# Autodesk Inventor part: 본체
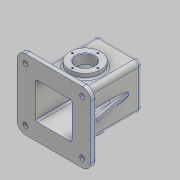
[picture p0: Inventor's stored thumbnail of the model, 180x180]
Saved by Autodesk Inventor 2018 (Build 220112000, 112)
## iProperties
Created: 2022-11
Part Number: 본체
Material: 알루미늄 6061
Document SubType Name: Modeling
Designer: home
Density: 2.7 g/cm^3
Appearance: 알루미늄 - 평지
Mass: 1126.74 g
Surface Area: 1013.84 cm^2
Volume: 417.312 cm^3
Author: home
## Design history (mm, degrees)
sketch "스케치1"
  geometry: L1 (-65, 47)-(-65, -47); L2 (-50, -62)-(50, -62); L3 (65, -47)-(65, 47); L4 (50, 62)-(-50, 62); L5 (-65, 62)-(65, -62); L6 (-65, -62)-(65, 62); A1 r 15 centre (50, 47) between (65, 47) and (50, 62); A2 r 15 centre (-50, 47) between (-50, 62) and (-65, 47); A3 r 15 centre (-50, -47) between (-65, -47) and (-50, -62); A4 r 15 centre (50, -47) between (50, -62) and (65, -47); 1 further point
  constraints: 12 end point, 8 point on circle, 8 point on line, 8 tangent, 4 centre point, 3 equal radius, 2 midpoint, 2 parallel, 1 perpendicular, 1 vertical
  dimensions: "d0" = 124 distance of L5.start L6.start; "d1" = 130 distance of L5.end L6.start; "d4" = 15 radius of A1
extrude "돌출1" new body sketch "스케치1" distance "d2" = 10; taper "d3" = 0 deg
sketch "스케치3"
  geometry: C1 r 4.5 at (-50, -47); C2 r 4.5 at (50, -47); C3 r 4.5 at (50, 47); C4 r 4.5 at (-50, 47); A1 r 15 centre (-50, -47) between (-65, -47) and (-50, -62) reference; A2 r 15 centre (50, -47) between (50, -62) and (65, -47) reference; A3 r 15 centre (50, 47) between (65, 47) and (50, 62) reference; A4 r 15 centre (-50, 47) between (-50, 62) and (-65, 47) reference; 1 further point
  constraints: 4 centre point, 4 coincident
  dimensions: "d5" = 9 diameter of C1; "d6" = 9 diameter of C2; "d7" = 9 diameter of C3; "d8" = 9 diameter of C4
extrude "돌출2" cut sketch "스케치3" extent not by distance; stored distance "d9" = 10; taper "d10" = 0 deg
sketch "스케치4"
  geometry: L1 (40, -40)-(40, 40); L2 (40, 40)-(-40, 40); L3 (-40, 40)-(-40, -40); L4 (-40, -40)-(40, -40); L5 (40, -40)-(-40, 40); L6 (40, 40)-(-40, -40); 1 further point
  constraints: 12 end point, 2 midpoint, 2 parallel, 1 perpendicular, 1 vertical
  dimensions: "d11" = 80 distance of L1.start L1.end; "d12" = 80 distance of L2.end L1.end
extrude "돌출3" join sketch "스케치4" distance "d13" = 107; taper "d14" = 0 deg
sketch "스케치5"
  geometry: C1 r 20 at (0, 0); 1 further point
  constraints: 1 centre point, 1 coincident
  dimensions: "d15" = 40 diameter of C1
extrude "돌출4" join sketch "스케치5" distance "d16" = 10; taper "d17" = -10 deg
sketch "스케치6"
  geometry: C1 r 20 at (0, 0) reference; C2 r 14 at (0, 0); 1 further point
  constraints: 1 centre point, 1 coincident
  dimensions: "d18" = 28 diameter of C2
extrude "돌출5" cut sketch "스케치6" distance "d19" = 4; taper "d20" = 0 deg
sketch "스케치7"
  geometry: C1 r 14 at (0, 0) reference; C2 r 10.5 at (0, 0); 1 further point
  constraints: 1 centre point, 1 coincident
  dimensions: "d21" = 21 diameter of C2
extrude "돌출6" cut sketch "스케치7" extent not by distance; stored distance "d22" = 4; taper "d23" = 0 deg
sketch "스케치8"
  geometry: L1 (40, -10)-(40, 45); C1 r 27.5 at (40, 45)
  constraints: 2 end point, 1 centre point, 1 coincident, 1 vertical
  dimensions: "d24" = 55 distance of L1.start L1.end; "d25" = 55 diameter of C1
extrude "돌출7" join sketch "스케치8" distance "d26" = 9; taper "d27" = 0 deg
sketch "스케치9" dims "d28" = 45
  geometry: C1 r 27.5 at (0, 0) reference; 3 further points
  constraints: 1 coincident, 1 vertical alignment, 2 other
hole "구멍1" sketch "스케치9" at (0, 22.5) diameter "d29" = 3.242; stored, may be unused: countersink angle "d33" = 90 deg, drill point angle "d35" = 118 deg; dims "d30" = 8, "d31" = 4, "d32" = 2, "d34" = 10
sketch "스케치10"
  geometry: C1 r 27.5 at (0, 0) reference; C2 r 16 at (0, 0); 1 further point
  constraints: 1 centre point, 1 coincident
  dimensions: "d39" = 32 diameter of C2
extrude "돌출8" cut sketch "스케치10" extent not by distance; stored distance "d40" = 9; taper "d41" = 0 deg
sketch "스케치11"
  geometry: L1 (-32, 32)-(-32, -32); L2 (-32, -32)-(32, -32); L3 (32, -32)-(32, 32); L4 (32, 32)-(-32, 32); L5 (-32, 32)-(32, -32); L6 (-32, -32)-(32, 32); 1 further point
  constraints: 12 end point, 2 midpoint, 2 parallel, 1 perpendicular, 1 vertical
  dimensions: "d42" = 64 distance of L1.start L1.end; "d43" = 64 distance of L2.end L1.end
extrude "돌출9" cut sketch "스케치11" distance "d44" = 109; taper "d45" = 0 deg
sketch "스케치12"
  geometry: L1 (55, 6.161)-(39.075, 96.478); L2 (39.075, 96.478)-(39.075, 6.161); L3 (-50, 0)-(50, 0) reference; L4 (39.075, 6.161)-(55, 6.161); L5 (65, 0)-(65, 10) reference; 1 further point
  constraints: 6 end point, 2 perpendicular
  dimensions: "d46" = 10 distance from line of L5 L1.start; "d47" = 100 deg angle of L4 L1
extrude "돌출10" join sketch "스케치12" stored distance "d48" = 10; taper "d49" = 0 deg
chamfer "모따기1" distance "d52" = 1; stored, may be unused: second distance "d53" = 2, angle "d54" = 45 deg
fillet "모깎기4" dims "d63" = 3
fillet "모깎기5" dims "d64" = 8, "d65" = 3
sketch "스케치14"
  geometry: L1 (72, -96)-(72, 0) reference; L2 (13.763, 18)-(50.237, 18) reference; 2 further points
  constraints: 1 other
  dimensions: "d68" = 40 distance from line of L1 point (32, -7); "d69" = 25 distance from line of L2 point (32, -7)
feature "엠보싱2" sketch "스케치14" dims "d0" = 124, "d1" = 130, "d4" = 15, "d6" = 9, "d66" = 0.5, "d67" = 0
fillet "모깎기6" dims "d70" = 3
fillet "모깎기7" dims "d71" = 3
node "솔리드1"
pattern_circular "원형 패턴1" dims angle "d37" = 360 deg
mirror "미러2"
mirror "미러3"
